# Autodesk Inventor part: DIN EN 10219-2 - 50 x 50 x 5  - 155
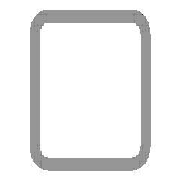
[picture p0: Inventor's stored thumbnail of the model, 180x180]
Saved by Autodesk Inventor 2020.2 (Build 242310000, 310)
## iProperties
_CCFamilyMember: 16
_CCFamilyDisplayName: DIN EN 10219-2 (Quadratisches Hohlprofil - Kaltgeformt) - Kaltgeformte, geschweißte Baustahl-Hohlprofile aus unlegiertem Feinkorn-Baustahl
_FrameMemberDoc: Frame Member File
_Version: 15.0.0
_GetPNFromCC: 1
IsCustomPart: 1
Created: 2019-11
Part Number: DIN EN 10219-2 - 50 x 50 x 5  - 155
Material: Stahl, weich
Description: Kaltgeformte, geschweißte Baustahl-Hohlprofile aus unlegiertem Feinkorn-Baustahl
Document SubType Name: Modeling
Standard: DIN
Designer: lutzd
Standard Revision: 2006-07
Standards Organization: DIN
Language: de-DE
Size Designation: 50 x 50 x 5
Categories: <MemberInstance><Categories><Category DisplayName="Profile" InternalName="089c4875-fa83-4c05-b084-43b9cc11f5ed" Mnemonic="GRDR"><CategoryParameter DisplayName="
Stock Number: 50 x 50 x 5
Mass: 1016.74 g
Surface Area: 534.796 cm^2
Volume: 129.521 cm^3
Density: 7.85 g/cm^3
Appearance: Semi-Polished(8)
G_W: 50,000 mm
G_H: 50,000 mm
Mass: 1,017 kg
VLT_Material: Stahl, weich
DocNumber: ADSK-014414
Folder: .
Dimensions: 50x50x155 mm
G_L: 155,000 mm
+A6155864-3115-4083-9D38-75BB5D0D57D8+SCHNITTDETAIL2: Schnittwinkel 90,00 grd
Title: Profil-Bauteil
Author: lutzd
Revision Number: -
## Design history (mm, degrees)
node "Startebene"
node "Endebene"
sketch "Skizze"
  geometry: L1 (-25, -15)-(-25, 15); L2 (-15, 25)-(15, 25); L3 (25, 15)-(25, -15); L4 (15, -25)-(-15, -25); L5 (-15, 20)-(15, 20); L6 (20, 15)-(20, -15); L7 (15, -20)-(-15, -20); L8 (-20, -15)-(-20, 15); L9 (0, 37.899)-(0, -37.899) reference; L10 (-37.899, 0)-(37.899, 0) reference; A1 r 10 centre (-15, -15) between (-25, -15) and (-15, -25); A2 r 10 centre (-15, 15) between (-15, 25) and (-25, 15); A3 r 10 centre (15, 15) between (25, 15) and (15, 25); A4 r 10 centre (15, -15) between (15, -25) and (25, -15); A5 r 5 centre (-15, 15) between (-15, 20) and (-20, 15); A6 r 5 centre (15, 15) between (20, 15) and (15, 20); A7 r 5 centre (15, -15) between (15, -20) and (20, -15); A8 r 5 centre (-15, -15) between (-20, -15) and (-15, -20)
  constraints: 16 end point, 16 point on circle, 8 centre point, 8 tangent, 4 parallel, 3 equal radius, 2 perpendicular, 7 other
  dimensions: "d7" = 10 radius of A1 (= G_IR); "d10" = 50 distance between parallel lines of L2 L4 (= G_H); "d11" = 50 distance between parallel lines of L1 L3 (= G_W); "d12" = 5 distance between parallel lines of L3 L6 (= G_T); "d15" = 25 distance between parallel lines of L2 L10 (= 0.5 x d10); "d16" = 25 distance between parallel lines of L9 L3 (= 0.5 x d11)
extrude "Körper" new body sketch "Skizze" stored distance "d3" = 155 (= G_L); taper "d4" = 0 deg
node "Driven Length"
  sketch "Sketch3"
    geometry: L1 (0, 0)-(10, 0) reference
    constraints: 2 end point, 1 horizontal
  workplane "Work Plane3"
  sketch "Sketch4"
    geometry: L1 (-2, 0)-(12, 0) reference; L2 (-2, 155)-(12, 155) reference
    dimensions: "d18" = 155 distance between parallel lines of L1 L2 (derived)
workplane "Arbeitsebene5"
feature "Trennen2"
body "Solid1"
other parameters: "G_W" = 50 [user parameter; used in 1 equation term], "G_H" = 50 [user parameter; used in 1 equation term], "G_T" = 5 [user parameter; used in 1 equation term], "G_IR" = 10 [user parameter; used in 1 equation term], "G_L" = 155 (= d18) [user parameter; used in 1 equation term], "G_OFFSET_START" = 0 [user parameter; used in 1 equation term], "G_OFFSET_END" = 0 [user parameter; used in 1 equation term], "d13" = 0 (computed from G_OFFSET_START), "d14" = 155 (= G_OFFSET_END + B_L), "B_L" = 155 [user parameter; used in 1 equation term], "d17" = 90 deg
